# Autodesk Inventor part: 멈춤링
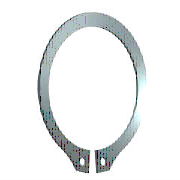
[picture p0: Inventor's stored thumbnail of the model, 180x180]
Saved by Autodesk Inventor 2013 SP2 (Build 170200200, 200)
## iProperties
Created: 2014-12
Part Number: 멈춤링
Material: 강, 연강
Description: 리테이닝 링(C형)
Document SubType Name: Modeling
Standard: KS B 1336
Designer: KYOUNG IL JANG
Standards Organization: KS
Language: ko-KR
Size Designation: 17 x 1
Categories: <MemberInstance><Categories><Category DisplayName="샤프트 부품" InternalName="7f7aeb1f-a693-4053-b835-cee3144e0d98" Mnemonic="SHFT"><Category DisplayName="써클립" Inter
Density: 7.86 g/cm^3
Mass: 0.979804 g
Surface Area: 3.83537 cm^2
Volume: 0.124657 cm^3
Company: 한국ATC센터
Author: KYOUNG IL JANG
IsCustomPart: 0
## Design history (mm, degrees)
sketch "스케치1"
  geometry: L1 (-6, 0)-(6, 0) reference; L2 (0, 20.189)-(0, -80.536) reference; L3 (-48.09, 0)-(48.09, 0) reference; L4 (-0.425, -16.589)-(-0.425, -20.289); L5 (-0.425, -6.54)-(-0.425, -13.29); L6 (-2.795, 2.2)-(3.672, 2.2); L7 (0.425, -6.54)-(0.425, -13.29); L8 (0.425, -16.589)-(0.425, -20.289); C1 r 0.85 at (-1.7, -18.452); C2 r 0.85 at (1.7, -18.452); A1 r 8.1 centre (0, -8.5) between (0.425, -16.589) and (-0.425, -16.589); A2 r 10.15 centre (0, -7.95) between (4.363, -17.114) and (-4.363, -17.114); A3 r 11.797 centre (0, -8.5) between (-1.986, -20.128) and (-0.425, -20.289); A4 r 1.7 centre (-1.7, -18.452) between (-3.397, -18.551) and (-1.986, -20.128); A5 r 1.7 centre (-5.094, -18.649) between (-3.397, -18.551) and (-4.363, -17.114); A6 r 1.7 centre (5.094, -18.649) between (4.363, -17.114) and (3.397, -18.551); A7 r 1.7 centre (1.7, -18.452) between (1.986, -20.128) and (3.397, -18.551); A8 r 11.797 centre (0, -8.5) between (0.425, -20.289) and (1.986, -20.128)
  constraints: 16 point on circle, 12 end point, 10 centre point, 9 symmetric about line, 5 point on line, 4 tangent, 3 coincident, 2 horizontal, 1 perpendicular, 1 vertical, 5 other
  dimensions: "d0" = 16.2 diameter of A1 (= ND); "d1" = 3.7 distance of L4.end L4.start (= SRB2); "d6" = 0.425 distance between parallel lines of L2 L5 (= 0.25 x SD5); "d7" = 2.2 distance between parallel lines of L6 L3 (= SRB1); "d8" = 0.55 distance of A1.centre A2.centre (= 0.25 x SRB1); "d9" = 1.7 radius of A4 (= SD5); "d10" = 1.7 radius of A5 (= SD5); "d11" = 1.275 distance from line of L4 A4.centre (= 0.75 x SD5); "d12" = 1.7 diameter of C1 (= SD5); "d13" = 1.7 diameter of C2 (= SD5); "d14" = 8.5 distance from line of A1.centre L1 (= 0.5 x WD)
extrude "본체" new body sketch "스케치1" distance "d2" = 1 (= SD); taper "d3" = 0 deg
workaxis "Work Axis1"
workplane "Work Plane1"
body "Solid1"
other parameters: "WD" = 17 (= WDMIN) [user parameter; used in 1 equation term], "SD" = 1 [user parameter; used in 1 equation term], "SRB1" = 2.2 [user parameter; used in 2 equation terms], "ND" = 16.2 [user parameter; used in 1 equation term], "SRB2" = 3.7 [user parameter; used in 1 equation term], "SD5" = 1.7 [user parameter; used in 6 equation terms], "d15" = 0, "d16" = 0, "d17" = 0, "d41" = 0, "d42" = 0, "WDMIN" = 17 [user parameter; used in 1 equation term], "SD3" = 15.7 [user parameter], "WDMAX" = 18 [user parameter]
